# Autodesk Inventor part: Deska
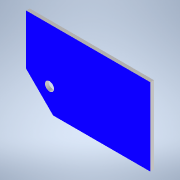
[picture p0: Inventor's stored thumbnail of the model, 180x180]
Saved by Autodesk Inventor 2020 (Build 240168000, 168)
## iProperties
Created: 2021-01
Part Number: Deska
Material: Všeobecné
Document SubType Name: Modeling
Designer: Pavel
Density: 1 g/cm^3
Appearance: Výchozí
Author: Pavel
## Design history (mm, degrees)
sketch "Náčrt1"
  geometry: L1 (15, 0)-(69, 0); L2 (69, 0)-(69, 43); L3 (69, 43)-(5, 43); L4 (0, 38)-(0, 15); L5 (0, 15)-(15, 0); L6 (0, 38)-(5, 43); C1 r 2.5 at (13, 13); 1 further point
  constraints: 12 end point, 2 parallel, 1 centre point, 1 horizontal, 1 perpendicular
  dimensions: "d1" = 45 deg angle of L1 L5; "d3" = 5 diameter of C1
extrude "Vysunutí1" new body sketch "Náčrt1" distance "d4" = 2; taper "d5" = 0 deg
node "Těleso1"
